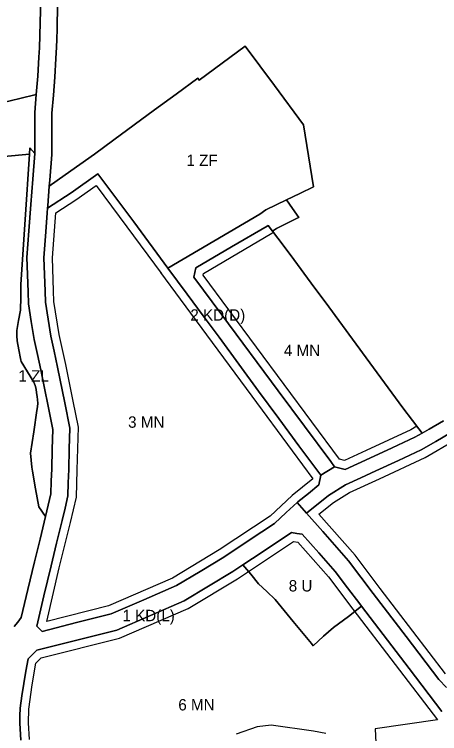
# Model space of a CAD drawing. Extents: x 7423691 to 7425475, y 5552085 to 5554331.
# Drawn here: x 7424385 to 7424685, y 5552921 to 5553427 of the extents above; entities that cross this region are included whole.
import ezdxf

# ---------------------------------------------------------------- set-up
doc = ezdxf.new("R2010")
doc.units = 0
for name, color, linetype in [('linia_zabudowy_nieprzekraczalna', 7, 'Continuous'), ('linie_rozgraniczajace', 7, 'Continuous'), ('oznaczenia_przeznaczen', 7, 'Continuous')]:
    doc.layers.add(name, color=color, linetype=linetype)

msp = doc.modelspace()

# ---------------------------------------------------------------- linework, layer by layer
at = {"layer": 'linia_zabudowy_nieprzekraczalna'}
for points in [[(7424595.37, 5553100.63), (7424580.77, 5553089.01), (7424565.21, 5553074.33), (7424529.38, 5553050.69), (7424496.55, 5553030.86), (7424451.46, 5553011.31), (7424408.02, 5553000.41), (7424416.91, 5553038.12), (7424424.73, 5553069.94), (7424428.94, 5553087.84), (7424429.51, 5553107.03), (7424430.39, 5553136.85), (7424426.73, 5553155.23), (7424421.44, 5553181.01), (7424416.9, 5553202.05), (7424413.09, 5553225.42), (7424412.85, 5553232.83), (7424412.08, 5553255.95), (7424414.41, 5553287.64), (7424428.53, 5553296.72), (7424442.75, 5553306.88), (7424464.44, 5553277.83), (7424488.53, 5553245.18), (7424488.11, 5553245.75), (7424502.01, 5553226.88), (7424524.53, 5553196.57), (7424552.3, 5553158.72), (7424580.76, 5553120.25), (7424595.31, 5553100.59)], [(7424668.58, 5553137.64), (7424664.31, 5553135.17), (7424632.99, 5553120.66), (7424617.62, 5553113.58), (7424614.21, 5553114.45), (7424536.22, 5553219.41), (7424518.08, 5553243.82), (7424518.34, 5553245.11), (7424566.51, 5553273.31), (7424567.3, 5553273.85)], [(7424688.62, 5552963.41), (7424642.68, 5553023.53), (7424625.06, 5553046.84), (7424599.57, 5553075.74), (7424609.77, 5553084), (7424621.21, 5553091.02), (7424642.22, 5553100.69), (7424674.46, 5553115.63), (7424695.37, 5553127.73)], [(7424395.91, 5552917.33), (7424395.1, 5552928.99), (7424395.34, 5552938.74), (7424397.84, 5552955.83), (7424400.47, 5552971.12), (7424404.13, 5552974.69), (7424459.21, 5552988.51), (7424507.58, 5553009.48), (7424542.2, 5553030.39), (7424581.82, 5553056.54), (7424584.86, 5553056.14), (7424606.46, 5553031.64), (7424623.57, 5553009.01), (7424683, 5552931.24)], [(7424683, 5552931.24), (7424639.14, 5552924.89), (7424639.61, 5552915.08)], [(7424604.41, 5552921.46), (7424595.75, 5552923.2), (7424566.11, 5552927.34), (7424556.1, 5552926.21), (7424541.26, 5552921.01)]]:
    msp.add_lwpolyline(points, dxfattribs=at)
at = {"layer": 'linie_rozgraniczajace'}
for points in [[(7424404.09, 5553447.74), (7424402.84, 5553403.8), (7424402.46, 5553397.12), (7424401.72, 5553383.77), (7424400.72, 5553370.96), (7424389.05, 5553368.17), (7424377.38, 5553365.38), (7424359.9, 5553359.31), (7424342.42, 5553353.25), (7424314.38, 5553344.13), (7424286.34, 5553335.02), (7424280.52, 5553333), (7424274.69, 5553330.99), (7424238.8, 5553313.52), (7424202.92, 5553296.05), (7424170.19, 5553280.04), (7424138.53, 5553264.56), (7424137.46, 5553264.03), (7424114.78, 5553252.97), (7424092.11, 5553241.91), (7423950.32, 5553563.7)], [(7424416.61, 5553502.1), (7424415.5, 5553417.06), (7424415.18, 5553409.65), (7424414.88, 5553404.17), (7424414.44, 5553396.31), (7424413.69, 5553382.97), (7424412.71, 5553370.32), (7424411.73, 5553357.68), (7424411.69, 5553343.22), (7424411.65, 5553328.75), (7424410.21, 5553310.68), (7424409.87, 5553306.52), (7424408.76, 5553292.61), (7424408.64, 5553291.07), (7424408.39, 5553287.63), (7424407.41, 5553274.34), (7424406.07, 5553256.07), (7424406.46, 5553244.35), (7424406.85, 5553232.63), (7424407.11, 5553224.84), (7424409.06, 5553212.88), (7424411, 5553200.93), (7424413.29, 5553190.35), (7424415.71, 5553179.14), (7424420.85, 5553154.04), (7424424.37, 5553136.35), (7424423.94, 5553121.78), (7424423.51, 5553107.21), (7424423.23, 5553097.91), (7424422.96, 5553088.62), (7424420.92, 5553079.98), (7424418.89, 5553071.35), (7424414.99, 5553055.43), (7424411.08, 5553039.52), (7424406.07, 5553018.29), (7424401.06, 5552997.06), (7424404.79, 5552993.36), (7424429.08, 5552999.51), (7424453.4, 5553005.61), (7424476.35, 5553015.56), (7424499.31, 5553025.52), (7424515.94, 5553035.57), (7424532.58, 5553045.62), (7424550.47, 5553057.42), (7424568.37, 5553069.23), (7424576.53, 5553076.84), (7424584.24, 5553084.05), (7424590.83, 5553076.57), (7424602.32, 5553063.54), (7424620.41, 5553043.04), (7424629.16, 5553031.47), (7424637.9, 5553019.9), (7424660.99, 5552989.69), (7424684.08, 5552959.48), (7424689.45, 5552954)], [(7424409.87, 5553306.52), (7424410.21, 5553310.68), (7424411.65, 5553328.75), (7424411.69, 5553343.22), (7424411.73, 5553357.68), (7424412.71, 5553370.32), (7424413.69, 5553382.97), (7424414.44, 5553396.31), (7424414.88, 5553404.17), (7424415.18, 5553409.65), (7424415.5, 5553417.06), (7424416.61, 5553502.1)], [(7424410.71, 5553143.5), (7424409.09, 5553151.66), (7424406.46, 5553164.48), (7424403.83, 5553177.3), (7424401.52, 5553188), (7424399.21, 5553198.7), (7424397.18, 5553211.18), (7424395.14, 5553223.67), (7424394.86, 5553232.23), (7424394.06, 5553256.31), (7424395.42, 5553274.92), (7424396.79, 5553293.53), (7424398.22, 5553311.39), (7424399.66, 5553329.32), (7424399.69, 5553343.7), (7424399.73, 5553358.16), (7424400.72, 5553370.96), (7424401.72, 5553383.77), (7424402.46, 5553397.12), (7424402.84, 5553403.8), (7424404.09, 5553447.74)], [(7424687.2, 5553141.48), (7424677.14, 5553135.66), (7424672.25, 5553132.83), (7424669.96, 5553135.83), (7424665.51, 5553141.66), (7424658.78, 5553150.48), (7424645.79, 5553168.12), (7424632.81, 5553185.75), (7424606.49, 5553221.47), (7424594.17, 5553238.21), (7424581.85, 5553254.95), (7424574.45, 5553264.92), (7424567.05, 5553274.88), (7424569.71, 5553276.7), (7424576.43, 5553279.98), (7424584.35, 5553283.84), (7424585.56, 5553284.41), (7424581.11, 5553290.66), (7424576.74, 5553296.82), (7424586.2, 5553301.35), (7424595.78, 5553305.94), (7424592.27, 5553327.78), (7424588.75, 5553349.61), (7424568.25, 5553377.19), (7424547.74, 5553404.77), (7424531.52, 5553392.85), (7424515.3, 5553380.93), (7424514.34, 5553382.36), (7424499.07, 5553371.23), (7424483.8, 5553360.1), (7424469.52, 5553349.51), (7424455.24, 5553338.92), (7424441.55, 5553328.98), (7424431.26, 5553321.69), (7424420.97, 5553314.39)], [(7424377.38, 5553365.38), (7424389.05, 5553368.17), (7424400.72, 5553370.96), (7424399.73, 5553358.16), (7424399.69, 5553343.7), (7424399.66, 5553329.32), (7424396.25, 5553333.45), (7424395.95, 5553328.82), (7424347.38, 5553324.56)], [(7424347.38, 5553324.56), (7424395.95, 5553328.82), (7424392.93, 5553283.09), (7424389.92, 5553237.36), (7424389.72, 5553228.29), (7424389.52, 5553219.23), (7424388.22, 5553212.04), (7424386.92, 5553204.86), (7424387.09, 5553201.21), (7424387.26, 5553197.56), (7424388.48, 5553191.36), (7424389.69, 5553185.15), (7424389.89, 5553184.15), (7424390.09, 5553183.15), (7424394.57, 5553175.89), (7424399.04, 5553168.62), (7424399.79, 5553166.16), (7424400.55, 5553163.69), (7424400.95, 5553161.12), (7424401.36, 5553158.56), (7424401.56, 5553156.22), (7424401.75, 5553153.87), (7424401.45, 5553151.3), (7424401.14, 5553148.73), (7424398.9, 5553133.74), (7424396.65, 5553118.74), (7424397.55, 5553108.88), (7424398.03, 5553106.08), (7424400.23, 5553093.55), (7424402.43, 5553081.01), (7424407.21, 5553074.09), (7424407.21, 5553074.09), (7424403.32, 5553058.24), (7424399.41, 5553042.33), (7424394.78, 5553022.71), (7424390.16, 5553003.09), (7424387.6, 5552999.9), (7424385.05, 5552996.71)], [(7424420.97, 5553314.39), (7424415.42, 5553310.45), (7424409.87, 5553306.52)], [(7424385.05, 5552996.71), (7424387.6, 5552999.9), (7424390.16, 5553003.09), (7424394.78, 5553022.71), (7424399.41, 5553042.33), (7424403.32, 5553058.24), (7424407.21, 5553074.09), (7424407.21, 5553074.09), (7424411, 5553090.19), (7424411.26, 5553098.88), (7424411.52, 5553107.56), (7424411.93, 5553121.45), (7424412.34, 5553135.34), (7424410.71, 5553143.5)], [(7424692.31, 5553132.89), (7424682, 5553126.92), (7424671.69, 5553120.96), (7424655.7, 5553113.55), (7424639.7, 5553106.14), (7424629.04, 5553101.23), (7424618.37, 5553096.32), (7424606.32, 5553088.92), (7424590.83, 5553076.57), (7424584.24, 5553084.05), (7424584.68, 5553084.46), (7424592.18, 5553090.43), (7424599.67, 5553096.39), (7424600.88, 5553103.15), (7424610.67, 5553109.16), (7424618.19, 5553107.24), (7424626.85, 5553111.23), (7424635.51, 5553115.21), (7424651.29, 5553122.53), (7424667.08, 5553129.84), (7424672.25, 5553132.83), (7424677.14, 5553135.66), (7424687.2, 5553141.48)], [(7424689.45, 5552954), (7424684.08, 5552959.48), (7424660.99, 5552989.69), (7424637.9, 5553019.9), (7424629.16, 5553031.47), (7424620.41, 5553043.04), (7424602.32, 5553063.54), (7424590.83, 5553076.57), (7424606.32, 5553088.92), (7424618.37, 5553096.32), (7424629.04, 5553101.23), (7424639.7, 5553106.14), (7424655.7, 5553113.55), (7424671.69, 5553120.96), (7424682, 5553126.92), (7424692.31, 5553132.89)], [(7424686.16, 5552936.99), (7424663.12, 5552967.14), (7424629.53, 5553011.09), (7424628.35, 5553012.64), (7424619.73, 5553024.04), (7424611.11, 5553035.44), (7424599.49, 5553048.61), (7424587.87, 5553061.79), (7424584.13, 5553062.29), (7424580.39, 5553062.78), (7424559.69, 5553049.13), (7424546.15, 5553040.19), (7424538.99, 5553035.47), (7424521.91, 5553025.15), (7424504.82, 5553014.83), (7424481.05, 5553004.52), (7424457.27, 5552994.21), (7424429.18, 5552987.16), (7424401.09, 5552980.12), (7424397.99, 5552977.08), (7424394.89, 5552974.05), (7424393.4, 5552965.41), (7424391.92, 5552956.77), (7424390.63, 5552948.01), (7424389.35, 5552939.25), (7424389.22, 5552934.05), (7424389.1, 5552928.86), (7424389.92, 5552916.88)], [(7424389.92, 5552916.88), (7424389.1, 5552928.86), (7424389.22, 5552934.05), (7424389.35, 5552939.25), (7424390.63, 5552948.01), (7424391.92, 5552956.77), (7424393.4, 5552965.41), (7424394.89, 5552974.05), (7424397.99, 5552977.08), (7424401.09, 5552980.12), (7424429.18, 5552987.16), (7424457.27, 5552994.21), (7424481.05, 5553004.52), (7424504.82, 5553014.83), (7424521.91, 5553025.15), (7424538.99, 5553035.47), (7424546.15, 5553040.19), (7424551.66, 5553033.52), (7424557.17, 5553026.84), (7424562.97, 5553021.29), (7424568.77, 5553015.73), (7424581.55, 5553000.29), (7424594.32, 5552984.86), (7424595.62, 5552983.29), (7424602.95, 5552989.95), (7424609.96, 5552996.06), (7424620.49, 5553003.82), (7424629.53, 5553011.09), (7424663.12, 5552967.14), (7424686.16, 5552936.99)]]:
    msp.add_lwpolyline(points, dxfattribs=at)
for points in [[(7424408.64, 5553291.07), (7424408.76, 5553292.61), (7424409.87, 5553306.52), (7424415.42, 5553310.45), (7424420.97, 5553314.39), (7424431.26, 5553321.69), (7424441.55, 5553328.98), (7424455.24, 5553338.92), (7424469.52, 5553349.51), (7424483.8, 5553360.1), (7424499.07, 5553371.23), (7424514.34, 5553382.36), (7424515.3, 5553380.93), (7424531.52, 5553392.85), (7424547.74, 5553404.77), (7424568.25, 5553377.19), (7424588.75, 5553349.61), (7424592.27, 5553327.78), (7424595.78, 5553305.94), (7424586.2, 5553301.35), (7424576.74, 5553296.82), (7424562.15, 5553289.7), (7424557.95, 5553286.84), (7424525.66, 5553267.79), (7424493.36, 5553248.74), (7424469.26, 5553281.4), (7424444.04, 5553315.18), (7424425.16, 5553301.68)], [(7424386.92, 5553204.86), (7424388.22, 5553212.04), (7424389.52, 5553219.23), (7424389.72, 5553228.29), (7424389.92, 5553237.36), (7424392.93, 5553283.09), (7424395.95, 5553328.82), (7424396.25, 5553333.45), (7424399.66, 5553329.32), (7424398.22, 5553311.39), (7424396.79, 5553293.53), (7424395.42, 5553274.92), (7424394.06, 5553256.31), (7424394.86, 5553232.23), (7424395.14, 5553223.67), (7424397.18, 5553211.18), (7424399.21, 5553198.7), (7424401.52, 5553188), (7424403.83, 5553177.3), (7424406.46, 5553164.48), (7424409.09, 5553151.66), (7424410.71, 5553143.5), (7424412.34, 5553135.34), (7424411.93, 5553121.45), (7424411.52, 5553107.56), (7424411.26, 5553098.88), (7424411, 5553090.19), (7424407.21, 5553074.09), (7424402.43, 5553081.01), (7424400.23, 5553093.55), (7424398.03, 5553106.08), (7424397.55, 5553108.88), (7424396.65, 5553118.74), (7424398.9, 5553133.74), (7424401.14, 5553148.73), (7424401.45, 5553151.3), (7424401.75, 5553153.87), (7424401.56, 5553156.22), (7424401.36, 5553158.56), (7424400.95, 5553161.12), (7424400.55, 5553163.69), (7424399.79, 5553166.16), (7424399.04, 5553168.62), (7424394.57, 5553175.89), (7424390.09, 5553183.15), (7424389.89, 5553184.15), (7424389.69, 5553185.15), (7424388.48, 5553191.36), (7424387.26, 5553197.56), (7424387.09, 5553201.21)], [(7424401.06, 5552997.06), (7424406.07, 5553018.29), (7424411.08, 5553039.52), (7424414.99, 5553055.43), (7424418.89, 5553071.35), (7424420.92, 5553079.98), (7424422.96, 5553088.62), (7424423.23, 5553097.91), (7424423.51, 5553107.21), (7424423.94, 5553121.78), (7424424.37, 5553136.35), (7424420.85, 5553154.04), (7424415.71, 5553179.14), (7424413.29, 5553190.35), (7424411, 5553200.93), (7424409.06, 5553212.88), (7424407.11, 5553224.84), (7424406.85, 5553232.63), (7424406.46, 5553244.35), (7424406.07, 5553256.07), (7424407.41, 5553274.34), (7424408.39, 5553287.63), (7424408.64, 5553291.07), (7424425.16, 5553301.68), (7424444.04, 5553315.18), (7424469.26, 5553281.4), (7424493.36, 5553248.74), (7424500.02, 5553239.69), (7424506.83, 5553230.45), (7424518.09, 5553215.29), (7424529.36, 5553200.13), (7424543.24, 5553181.2), (7424557.13, 5553162.28), (7424571.36, 5553143.05), (7424585.58, 5553123.82), (7424593.23, 5553113.49), (7424600.88, 5553103.15), (7424599.67, 5553096.39), (7424592.18, 5553090.43), (7424584.68, 5553084.46), (7424584.24, 5553084.05), (7424576.53, 5553076.84), (7424568.37, 5553069.23), (7424550.47, 5553057.42), (7424532.58, 5553045.62), (7424515.94, 5553035.57), (7424499.31, 5553025.52), (7424476.35, 5553015.56), (7424453.4, 5553005.61), (7424429.08, 5552999.51), (7424404.79, 5552993.36)], [(7424493.36, 5553248.74), (7424525.66, 5553267.79), (7424557.95, 5553286.84), (7424562.15, 5553289.7), (7424576.74, 5553296.82), (7424581.11, 5553290.66), (7424585.56, 5553284.41), (7424584.35, 5553283.84), (7424576.43, 5553279.98), (7424569.71, 5553276.7), (7424567.05, 5553274.88), (7424563.92, 5553278.8), (7424563.3, 5553278.38), (7424538.15, 5553263.66), (7424513, 5553248.93), (7424511.67, 5553242.39), (7424531.4, 5553215.84), (7424571.03, 5553162.5), (7424607.98, 5553112.77), (7424610.67, 5553109.16), (7424600.88, 5553103.15), (7424593.23, 5553113.49), (7424585.58, 5553123.82), (7424571.36, 5553143.05), (7424557.13, 5553162.28), (7424543.24, 5553181.2), (7424529.36, 5553200.13), (7424518.09, 5553215.29), (7424506.83, 5553230.45), (7424500.02, 5553239.69)], [(7424511.67, 5553242.39), (7424513, 5553248.93), (7424538.15, 5553263.66), (7424563.3, 5553278.38), (7424563.92, 5553278.8), (7424567.05, 5553274.88), (7424574.45, 5553264.92), (7424581.85, 5553254.95), (7424594.17, 5553238.21), (7424606.49, 5553221.47), (7424632.81, 5553185.75), (7424645.79, 5553168.12), (7424658.78, 5553150.48), (7424665.51, 5553141.66), (7424669.96, 5553135.83), (7424672.25, 5553132.83), (7424667.08, 5553129.84), (7424651.29, 5553122.53), (7424635.51, 5553115.21), (7424626.85, 5553111.23), (7424618.19, 5553107.24), (7424610.67, 5553109.16), (7424607.98, 5553112.77), (7424571.03, 5553162.5), (7424531.4, 5553215.84)], [(7424546.15, 5553040.19), (7424559.69, 5553049.13), (7424580.39, 5553062.78), (7424584.13, 5553062.29), (7424587.87, 5553061.79), (7424599.49, 5553048.61), (7424611.11, 5553035.44), (7424619.73, 5553024.04), (7424628.35, 5553012.64), (7424629.53, 5553011.09), (7424620.49, 5553003.82), (7424609.96, 5552996.06), (7424602.95, 5552989.95), (7424595.62, 5552983.29), (7424594.32, 5552984.86), (7424581.55, 5553000.29), (7424568.77, 5553015.73), (7424562.97, 5553021.29), (7424557.17, 5553026.84), (7424551.66, 5553033.52)]]:
    msp.add_lwpolyline(points, close=True, dxfattribs=at)

# ---------------------------------------------------------------- texts
at = {"layer": 'oznaczenia_przeznaczen'}
for s, p in [('1 ZF', (7424506.37, 5553320.58)), ('2 KD(D)', (7424509.13, 5553211.84)), ('4 MN', (7424574.94, 5553186.9)), ('1 ZL', (7424388.08, 5553169.03)), ('3 MN', (7424465.31, 5553136.55)), ('8 U', (7424578.38, 5553021.4)), ('1 KD(L)', (7424461.32, 5553000.51)), ('1 KD(L)', (7424461.32, 5553000.51)), ('6 MN', (7424500.65, 5552937.77))]:
    msp.add_text(s, height=8, dxfattribs=at).set_placement(p)

doc.saveas('drawing.dxf')
